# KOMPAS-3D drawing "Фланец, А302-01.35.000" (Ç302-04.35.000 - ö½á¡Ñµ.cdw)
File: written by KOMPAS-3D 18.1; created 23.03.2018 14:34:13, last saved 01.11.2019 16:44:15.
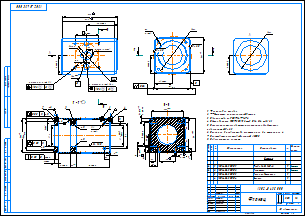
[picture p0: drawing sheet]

Sheet 1: A2, landscape

Document properties: Автор: Милов; Масса: 8.08129; Полное имя файла: ..\3Д ПВХ\А302-01.35.000 - Фланец.a3d

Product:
- Part/product: Фланец  | designation А302-01.35.000  | pos. 0
    Масса: 8.26617
    Раздел спецификации: Сборочные единицы
    Форматы листов документа: 2xA3
    Примечание: @100~)2xA3
    source file: ..\3Д ПВХ\А302-01.35.000 - Фланец.cdw
  - Component [detail]: Пластина  | designation А302-00.35.002  | pos. 2  | Масса: 0.697075; Раздел спецификации: Детали; Форматы листов документа: A4; Примечание: Заим.; source file: ..\3Д\А302-00.35.002 - Пластина.m3d
  - Component [detail]: Труба 140х140х4  | designation А302-00.35.001  | pos. 1  | Масса: 4.39548; Раздел спецификации: Детали; Форматы листов документа: A4; Примечание: Заим.; source file: ..\3Д\А302-00.35.001 - Труба 140х140х4.m3d
- Part/product: Фланец  | designation А302-04.35.000  | pos. 0
    Масса: 8.08129
    Раздел спецификации: Сборочные единицы
    Форматы листов документа: 2xA3
    Примечание: @100~)2xA3
    source file: ..\А302-04.00.000 - Мембранный насос ASTRA-302-PP Чертежи\А302-04.35.000 - Фланец.cdw, А302-04.35.000 - Фланец.cdw
  - Component [detail]: Стенка  | designation А302-04.35.004  | pos. 4  | Масса: 0.256038; Раздел спецификации: Детали; source file: ..\3Д ПВХ\А302-04.35.004 - Стенка.m3d
  - Component [detail]: Опора подшипника  | designation А302-04.35.003  | pos. 3  | Масса: 2.1523; Раздел спецификации: Детали; source file: ..\3Д ПВХ\А302-04.35.003 - Опора подшиника.m3d
  - Component [detail]: Труба 140х140х6  | designation А302-04.35.001  | pos. 1  | Масса: 4.48359; Раздел спецификации: Детали; Форматы листов документа: A4; Примечание: Заим.
  - Component [detail]: Пластина  | designation А302-04.35.002  | pos. 2  | Масса: 1.18936; Раздел спецификации: Детали; Форматы листов документа: A4; Примечание: Заим.
- Part/product: Фланец  | designation А302-05.35.000  | pos. 0
    Масса: 15.1675
    Раздел спецификации: Сборочные единицы
    Форматы листов документа: 2xA3
    Примечание: @100~)2xA3
    source file: ..\А302-04.00.000 - Мембранный насос ASTRA-302-PP Чертежи\А302-04.35.000 - Фланец.cdw
  - Component [detail]: Пластина  | designation А302-05.35.002  | pos. 2  | Масса: 0.658749; Раздел спецификации: Детали; Форматы листов документа: A4; Примечание: Заим.
  - Component [detail]: Труба 140х140х6  | designation А302-05.35.001  | pos. 1  | Масса: 2.81713; Раздел спецификации: Детали; Форматы листов документа: A4; Примечание: Заим.
  - Component [detail]: Опора подшиника  | designation А302-05.35.003  | pos. 7  | Масса: 10.2382; Раздел спецификации: Детали
  - Component [detail]: FB 063  | pos. 11  | Масса: 1.71461; Раздел спецификации: Детали; source file: ..\3Д ПВХ\FB 063 .m3d

Title block, sheet 1: Наименование: Фланец; designation: А302-04.35.000; Масса: 8,08; scale: 1:2; Количество листов документа: 1; organisation: АО «Астерион»; Форматы листов документа: A2; stored path: \\192.168.87.28\Konstructor_doc\Мембранные насосы\Мембранный электропривод\А302-00.00.000 - ASTRA-302 (МЭ200)\Чертежи\А302-00.35.000 - Фланец.cdw; Разработал: Лифлянд; Проверил: Борисенко; Т. контр.: Лучихин; Утвердил: Григорьева

Views: Спереди 5, Спереди, Проекционный вид 8, Разрез Б-Б, Разрез 13, Проекционный вид 14, Вид по стрелке 15, Вид по стрелке А
Referenced files in D:\Мембранные насосы\Мембранный электропривод\А302-00.00.000 - ASTRA-302 (МЭ200)\3Д ПВХ\: А302-01.35.000 - Фланец.a3d, А302-04.35.003 - Опора подшиника.m3d, А302-04.35.004 - Стенка.m3d, FB 063 .m3d
Referenced files in D:\Мембранные насосы\Мембранный электропривод\А302-00.00.000 - ASTRA-302 (МЭ200)\3Д\: А302-00.35.001 - Труба 140х140х4.m3d, А302-00.35.002 - Пластина.m3d, А302-00.35.000 - Фланец.a3d
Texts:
  Ra 2,5
  Ra 1,25
  Штриховая мини
  Стили документа
  Труба 140х140х4
  Заим.
  Пластина
  Труба 140х140х6
  Опора подшипника
  Стенка
Dimensions and other numbers on the sheet: 140; 72±0,2; 69,5±0,2; 139; 0,03; 0; 2 группы по 2 отв.; 9; 215; 92±0,2; 200; -6Н/0,5 45; 4; 10,25; 21; 121,8±0,1; 14,5; 34; 20; 1; 128; 30; 6; 10; 4 фаски; 26; 22; 8; 4 отв.; 63; 134; 80; 0,05; 2; 3; 25; 100; 5; 115; 15±0,2; 47±0,2; 0,06; 150; 120; 1:2; 8,08; 01.10.2019

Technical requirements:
  *Размеры для справок.
  **Уточнить по сопрягаемой детали.
  Сварные швы по ГОСТ 14771-76.
  Общие допуски ГОСТ 30893.2-mK (H14, h14,  t2/2).
  Неуказанная шероховатоть механически обработанных
  поверхностей Ra 6,3.
  Опору поз. 3 приварить до пластины поз. 2 и стенки поз. 4.
  Окрашивать порошковой краской А5005.
  Поверхность не красить.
